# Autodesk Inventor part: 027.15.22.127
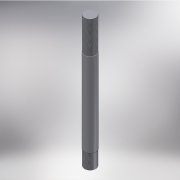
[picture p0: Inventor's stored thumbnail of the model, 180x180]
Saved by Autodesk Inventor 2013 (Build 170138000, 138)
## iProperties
Shininess: 64.0
Length Units: 11269
Angle Units: 11279
Time Units: 11290
Mass Units: 11283
Length Display Precision: 3
Angle Display Precision: 2
Created: 2002-02
Part Number: 027.15.22.127
Material: Steel, Mild
Document SubType Name: Modeling
Designer: SOleg
Density: 7.86 g/cm^3
Density: 0.0
Volumn: 0.0
Area: 0.0
PropertySet Name: Model Information
Control State: 0
Master: False
Checked Out: True
Checked Out Date: 2008-10-15
Last Check In Date: 2008-10-15
Author: SOleg
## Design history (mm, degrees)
sketch "Sketch1"
  geometry: C1 r 13.5 at (0, 0)
  constraints: 1 centre point
  dimensions: "d0" = 27 diameter of C1
extrude "Extrusion1" new body sketch "Sketch1" distance "d1" = 78; taper "d2" = 0 deg
sketch "Sketch2"
  geometry: C1 r 13.5 at (0, 0) reference; C2 r 14 at (0, 0)
  constraints: 1 centre point, 1 coincident
  dimensions: "d5" = 28 diameter of C2
extrude "Extrusion2" join sketch "Sketch2" distance "d3" = 201; taper "d4" = 0 deg
sketch "Sketch3"
  geometry: C1 r 14 at (0, 0) reference; C2 r 13.5 at (0, 0)
  constraints: 1 centre point, 1 coincident
  dimensions: "d6" = 27 diameter of C2
extrude "Extrusion3" join sketch "Sketch3" distance "d7" = 36; taper "d8" = 0 deg
thread "Thread1" dims "d9" = 10, "d10" = 0
thread "Thread2" dims "d11" = 10, "d12" = 0
body "Solid1"
